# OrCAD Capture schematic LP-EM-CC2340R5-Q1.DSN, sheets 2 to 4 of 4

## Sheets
2 2_Peripherals: size A3
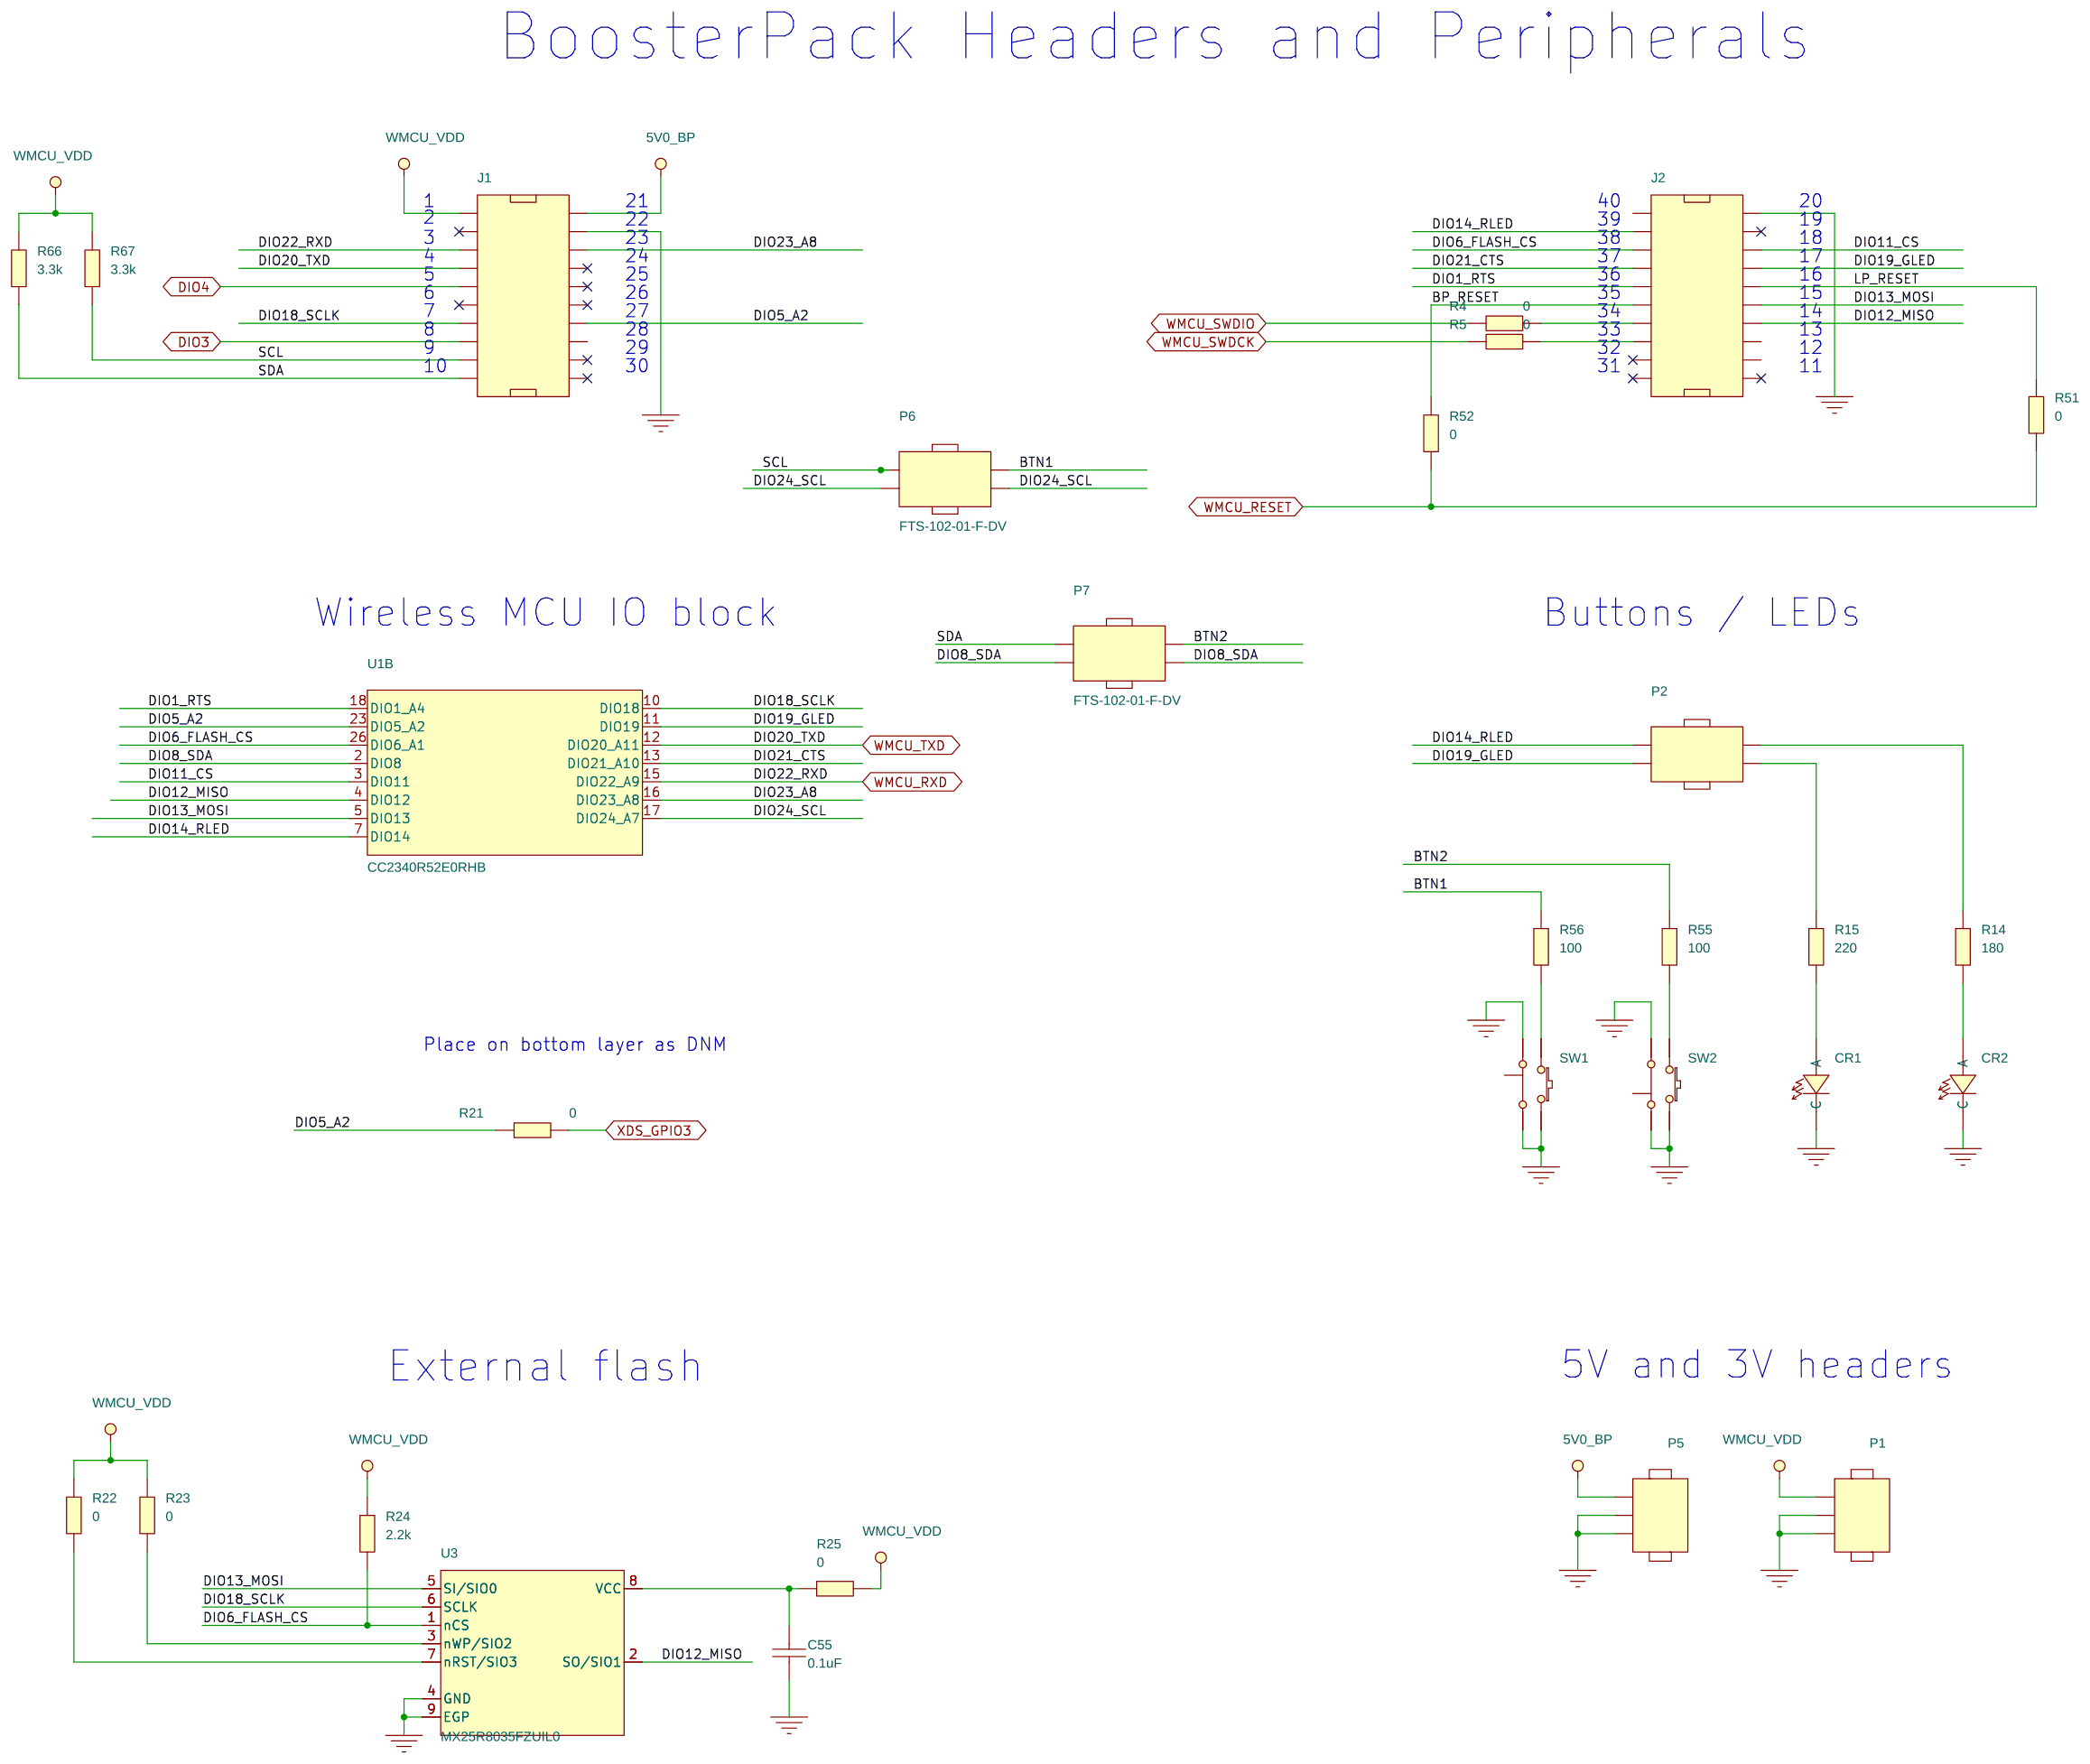
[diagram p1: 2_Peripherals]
3 3_Debugger Interface: size A3
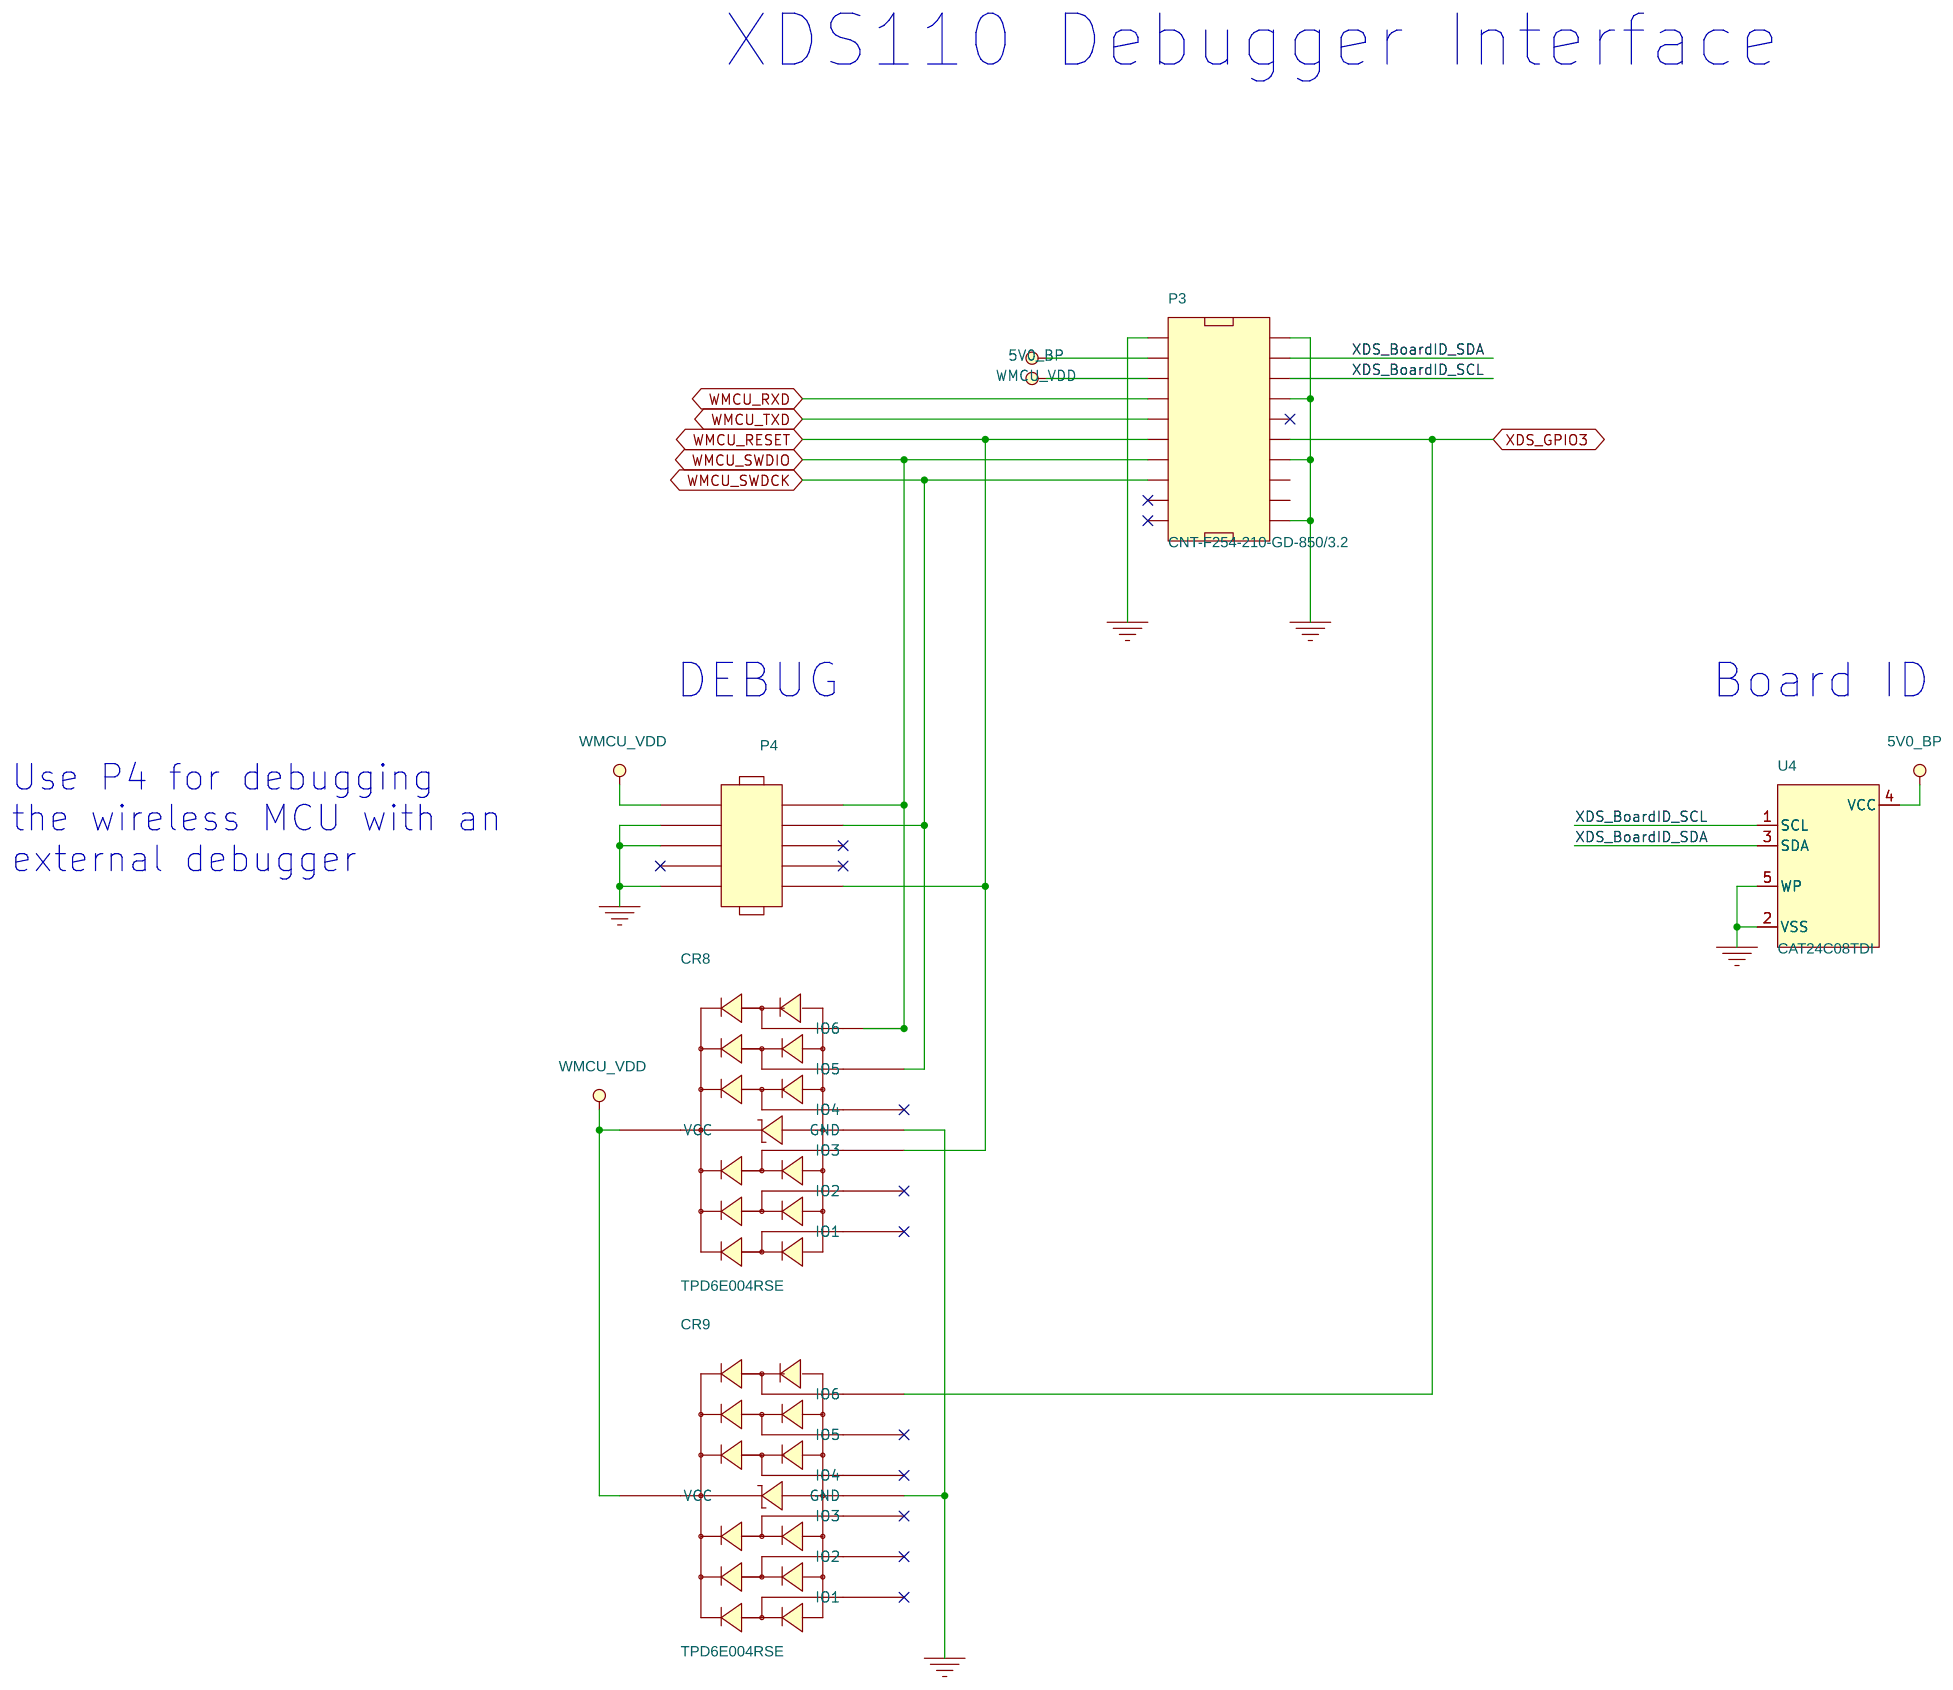
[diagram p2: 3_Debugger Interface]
4 4_Mech: size A3
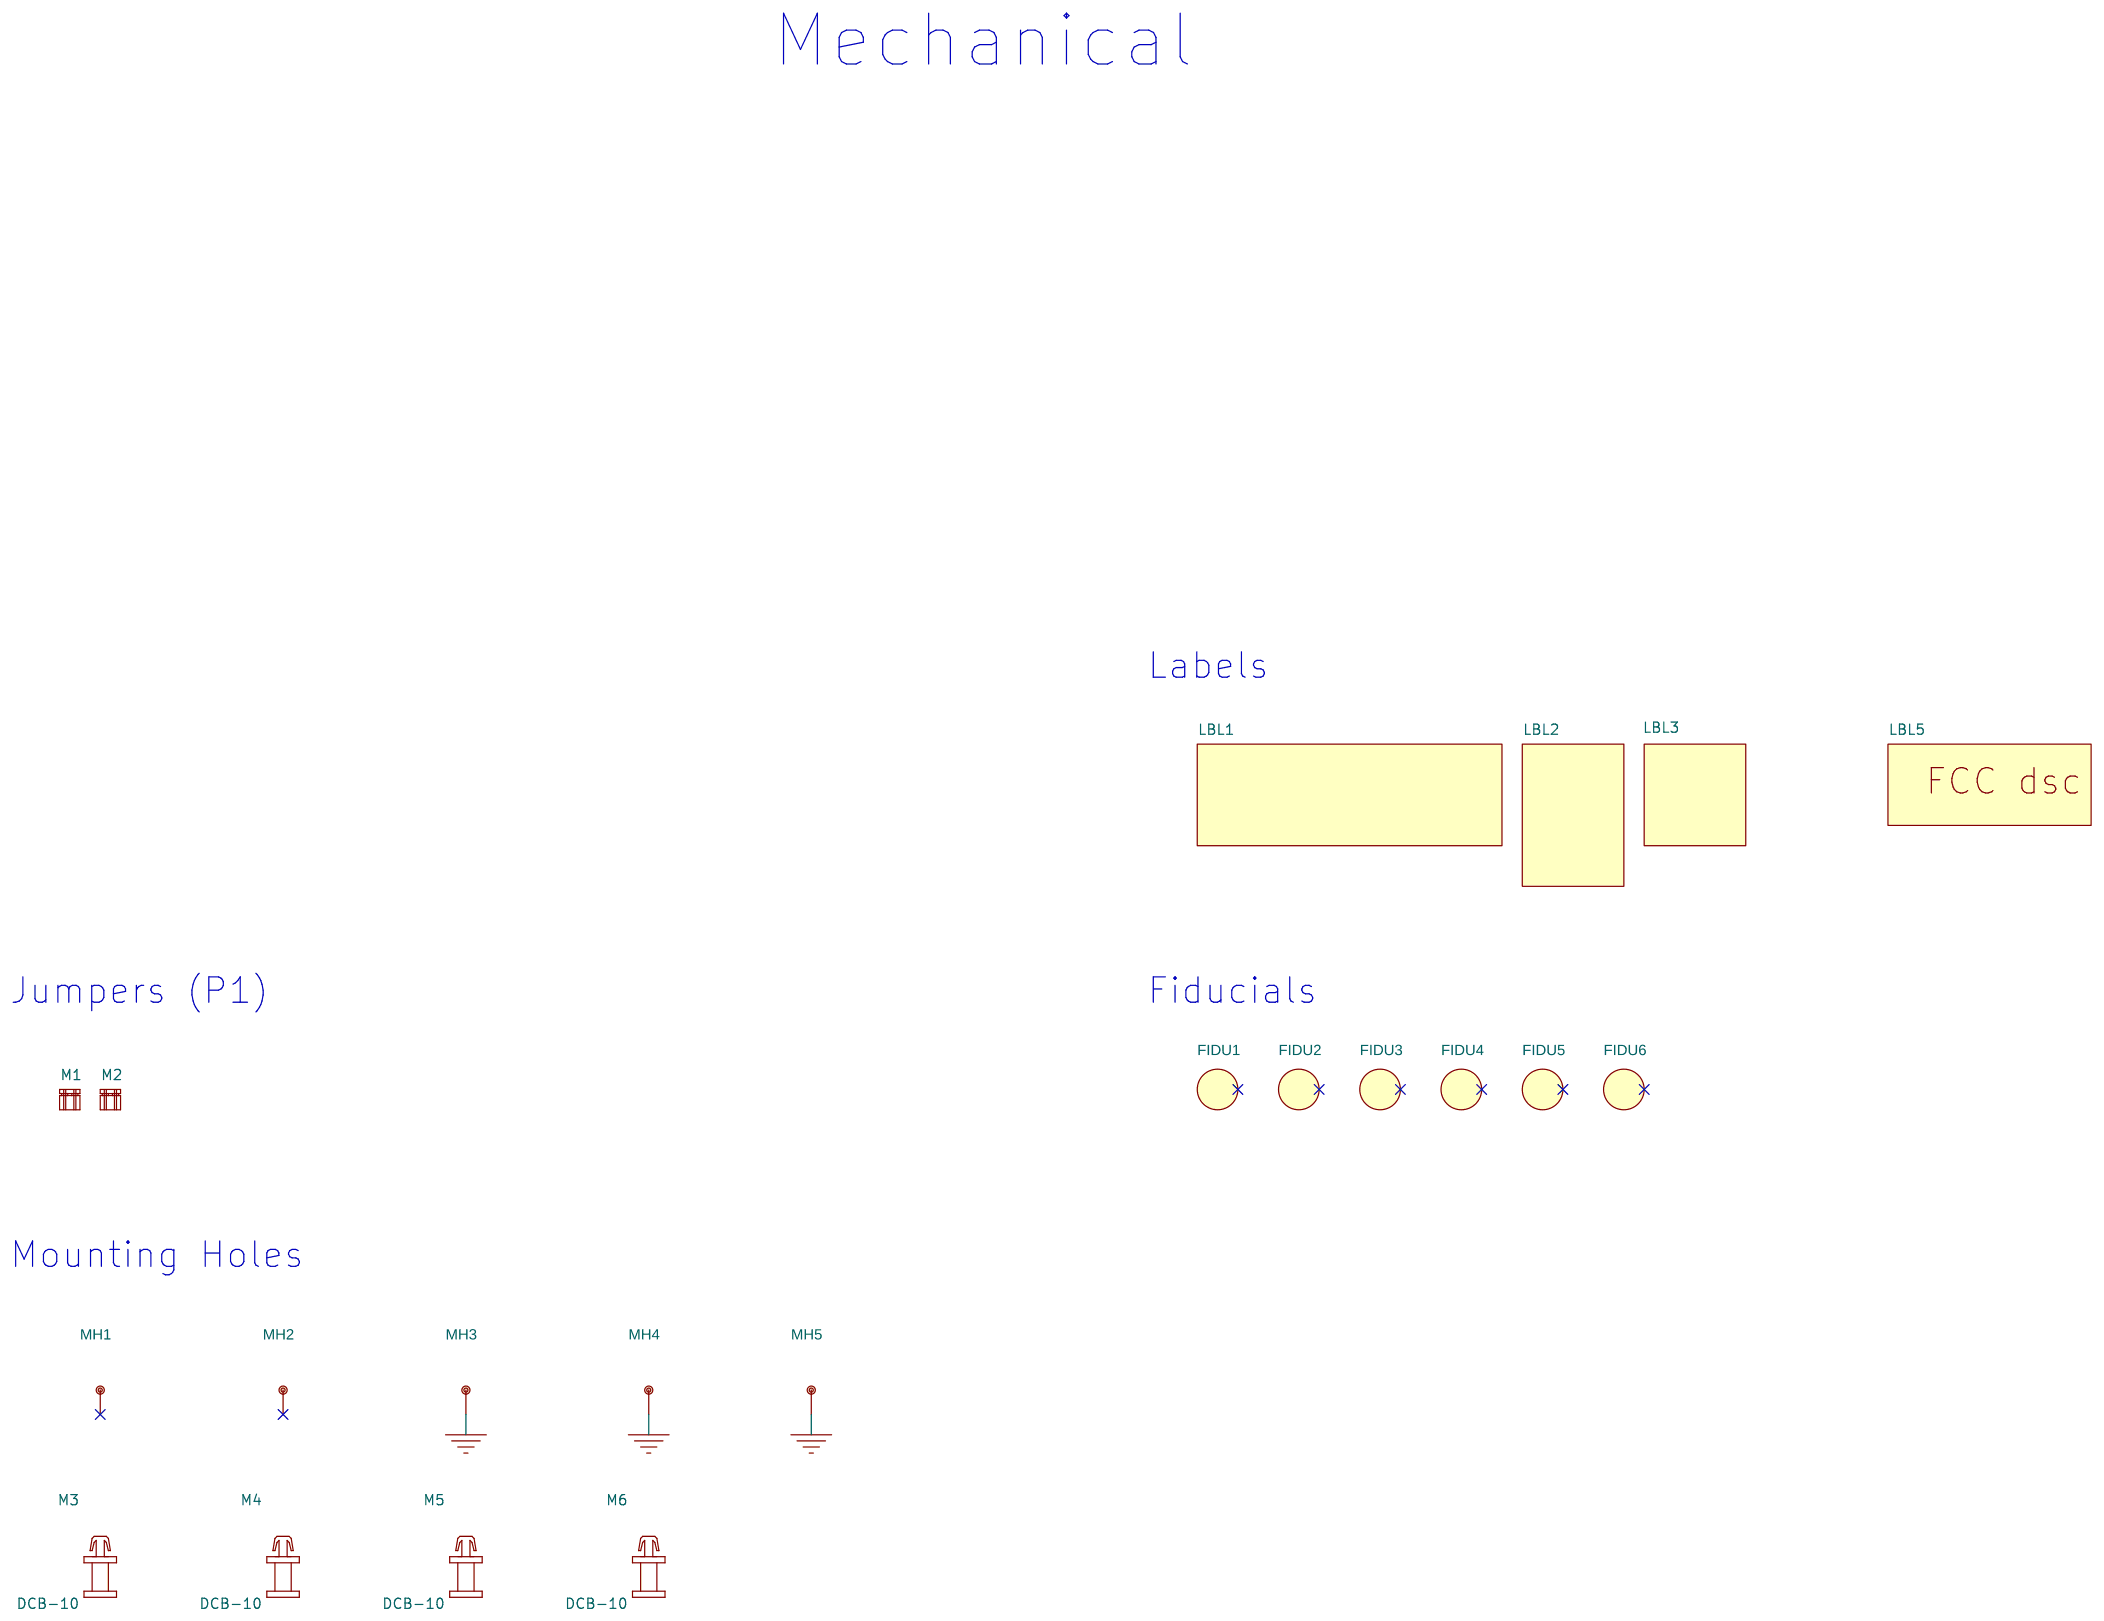
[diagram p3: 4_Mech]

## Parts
sheet 2_Peripherals
C55  0.1uF  [CAPC0603X35B2N]
CR1  LPL296-J2L2-25  [LEDC1707X65N]
CR2  LS L296-P2Q2-1  [LEDC1708X67N]
J1  SSQ-110-23-L-D  [SAMTEC_SSQ11023LD_A2B]
J2  SSQ-110-23-L-D  [SAMTEC_SSQ11023LD_A2B]
P1  BB02-HC031-KB1-603000  [GRADCONN_BB02HC031KB1603000_A2B]
P2  BB02-HJ041-KB1-603000  [GRADCONN_BB02HJ041KB1603000_A2B]
P5  BB02-HC031-KB1-603000  [GRADCONN_BB02HC031KB1603000_A2B]
P6  FTS-102-01-F-DV  [SAMTEC_FTS10201FDV_A2N]
P7  FTS-102-01-F-DV  [SAMTEC_FTS10201FDV_A2N]
R4  0  [RESC1608X55A2N]
R5  0  [RESC1608X55A2N]
R14  180  [RESC1005X40B2N]
R15  220  [RESC1005X40B2N]
R21  0  [RESC1608X55A2N]
R22  0  [RESC1608X55A2N]
R23  0  [RESC1608X55A2N]
R24  2.2k  [RESC1005X40B2N]
R25  0  [RESC1608X55A2N]
R51  0  [RESC1608X55A2N]
R52  0  [RESC1608X55A2N]
R55  100  [RESC1005X40B2N]
R56  100  [RESC1005X40B2N]
R66  3.3k  [RESC1005X40B2N]
R67  3.3k  [RESC1005X40B2N]
SW1  1188E-1K2  [SW_1188E1K2V_A2N]
SW2  1188E-1K2  [SW_1188E1K2V_A2N]
U1  CC2340R52E0RHB  [QFNFC50P500X500X100-33B2N]  (sections A,B)
U3  MX25R8035FZUIL0  [SON50P300X200X60-9B2N]
sheet 3_Debugger Interface
CR8  TPD6E004RSE  [QFNFC50P150X150X60-8A2N]
CR9  TPD6E004RSE  [QFNFC50P150X150X60-8A2N]
P3  CNT-F254-210-GD-850/3.2  [CNT_CNTF254210GD85032_A2B]
P4  FTSH-105-01-F-DV-K  [SAMTEC_FTSH-105-01-F-DV-K-10L]
U4  CAT24C08TDI  [SOT95P280X100-5A2N]
sheet 4_Mech
FIDU1  FIDU_1.27mm  [FID127X142]
FIDU2  FIDU_1.27mm  [FID127X142]
FIDU3  FIDU_1.27mm  [FID127X142]
FIDU4  FIDU_1.27mm  [FID127X142]
FIDU5  FIDU_1.27mm  [FID127X142]
FIDU6  FIDU_1.27mm  [FID127X142]
LBL1  TI_LOGO  [TI_LOGO_1]
LBL2  TRASH_7mm  [TRASH_7MM]
LBL3  ESD_LABEL_5x5mm  [ESD_LABEL_5x5]
LBL5  LABEL_FOR_EVALUATION_ONLY  [LABEL_FOR_EVALUATION_ONLY]
M1  SNT-100-BK-G  [SAMTEC_SNT100BKG]
M2  SNT-100-BK-G  [SAMTEC_SNT100BKG]
M3  DCB-10  [MECH_DCB10_A2B]
M4  DCB-10  [MECH_DCB10_A2B]
M5  DCB-10  [MECH_DCB10_A2B]
M6  DCB-10  [MECH_DCB10_A2B]
MH1  HOLE_3.2mm_PTH  [MTG320_380]
MH2  HOLE_3.2mm_PTH  [MTG320_380]
MH3  HOLE_3.2mm_PTH  [MTG320_380]
MH4  HOLE_3.2mm_PTH  [MTG320_380]
MH5  HOLE_1.1mm_PTH  [MTG110_170]

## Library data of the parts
C55 = CAPACITOR: CAPACITOR, CERAMIC X7S, 0.1uF, 10V, -10%/+10%, -55DEGC/+125DEGC, 0201, SMD; ALT_SYMBOLS: CAPC0603X35B2L,CAPC0603X35B2M; Additional Datasheet URL: https://search.murata.co.jp/Ceramy/image/img/A01X/G101/ENG/GRM033C71A104KE14-01A.pdf; AutoDoc File: https://notefied-dynamic-precision.com/DB/Apps/Desktop/Item/Object.aspx?id=115293; BU Name: TEXAS INSTRUMENTS NORWAY; Budgetary Price: 0.01328 USD; Client Status: UNDER_REVIEW; Datasheet URL: https://www.murata.com/-/media/webrenewal/support/library/catalog/products/capacitor/ceramiccapacitor/c02e.ashx?la=en-gb; Datasheet URL 1: http://psearch.en.murata.com/capacitor/product/GRM155R71E104KE14%23.pdf; Datasheet URL 2: http://search.murata.co.jp/Ceramy/image/img/w_hinm/L0005E.pdf; Definied Quality: INDUSTRIAL; Dielectric Type: X7S; Esd Level: N/A; Lead Time: 23; LifeCycle Status: ACTIVE; MPN: CAPACITOR_0402_100nF_X7R_M_+/-10%_10V; MPN Status: ACTIVE; MSL: N/A; MTBF: N/A; MTBF Standard: N/A; Manufacturer: MANUFACTURER SELECTION; Mass: 0.00033g; Max Oper Temp: +125DEGC; Max Tol: +10%; Maximum Operating Temperature: +125DEGC; Maximum Tolerance: +10%; Min Oper Temp: -55DEGC; Min Tol: -10%; Minimum Operating Temperature: -55DEGC; Minimum Tolerance: -10%; Mounting Type: SMD; NOTE Status: PREFERRED; NOTEfied URL: https://notefied-dynamic-precision.com/NOTEfiedWebInterface/part/show?partNumber=02-10308; Old Footprint: CAPC1005X60N; PCB Package: 0201; Packing Size: 15000; Packing Type: Tape & Reel; Part Number: 02-10308; Part Type: Capacitor|CERAMIC|0201|STANDARD; REACH/SVHC Compliance: Compliant; REACH/SVHC Details: SVHC List Version Jan 19, 2021; REACH/SVHC Source: REACH Declaration; REACH/SVHC Status: Unaffected; REACH/SVHC_COMPLIANCE: COMPLIANT; REACH/SVHC_DETAILS: SVHC LIST VERSION Jun 20, 2016; REACH/SVHC_SOURCE: REACH DECLARATION; REACH/SVHC_STATUS: UNAFFECTED; ROHS: Compliant; Rated Voltage: 10V; Revision: R001; RoHS Status: ROHS_COMPLIANT; Rtd Voltage: 25V; Status: Released; Texas Part Status: Under Review; Type: Capacitor; Vendor: MURATA; Vendor Part Number: GRM033C71A104KE14D; Vendor Part Status: Active; WEIGHT: 0.0016g
CR1 = LED: OPTO, LED, InGaAlP, GREEN, 560nm, 2V, 0.02A, 0603, SMD; ALT_SYMBOLS: LEDC1707X65L,LEDC1707X65M; Additional Datasheet URL: https://www.osram.com/ecat/SMARTLED%C2%AE%200603%20LP%20L296/com/en/class_pim_web_catalog_103489/prd_pim_device_2190983/; AutoDoc File: http://notefied-dynamic-precision.com/DB/Apps/Desktop/Item/Object.aspx?id=81622; Budget Currency: USD; Budget Price: 0.1263; CLASS: IC; Country of Origin: Missing Info; Datasheet URL: https://dammedia.osram.info/media/resource/hires/osram-dam-5662674/LP%20L296_EN.pdf; Datasheet URL 1: N/A; Datasheet URL 2: http://catalog.osram-os.com/jsp/download.jsp?rootPath=/media/&name=LP_L296.pdf&docPath=Graphics/00077128_0.pdf&url=/media//_en/Graphics/00077128_0.pdf; Definied Quality: INDUSTRIAL; Esd Level: HBM 2kV; FPLIST: LEDC1707X65N,LEDC1707X65L,LEDC1707X65M; MPN: LP L296-J2L2-25; MPN Status: NRND; MSL: 2; MTBF: N/A; MTBF Standard: N/A; Manufacturer: OSRAM; Mass: 0.0016g; Max Oper Temp: +100DEGC; Maximum Operating Temperature: +100DEGC; Min Oper Temp: -40DEGC; Minimum Operating Temperature: -40DEGC; Mounting Type: SMD; NOTE Status: NOT_PREFERRED; NOTEfied URL: https://notefied-dynamic-precision.com/NOTEfiedWebInterface/part/show?partNumber=15-01023; PCB Package: 0603; Packing Size: 5000; Packing Type: Tape & Reel; Part Number: 15-01023; Part Type: Opto|LED|0603; REACH/SVHC Compliance: Compliant; REACH/SVHC Details: SVHC List Version Jan 12, 2017; REACH/SVHC Source: REACH Declaration; REACH/SVHC Status: Unaffected; ROHS: Compliant; Rated Current: 0.02A; Rated Voltage: 2V; Revision: R029; RoHS Status: ROHS_COMPLIANT; Rtd Current: 0.02A; Rtd Power: 0.08W; Rtd Voltage: 2V; Status: Released; Type: Opto; Vendor: OSRAM; Vendor Part Number: LP L296-J2L2-25; Vendor Part Status: Active; WEIGHT: 0.002g
CR2 = LED: OPTO, LED, RED, 630nm, 2V, 0.02A, 0603, SMD; ALT_SYMBOLS: LEDC1708X67L,LEDC1708X67M; Additional Datasheet URL: https://www.osram.com/ecat/SMARTLED%C2%AE%200603%20LS%20L296/com/en/class_pim_web_catalog_103489/prd_pim_device_2190979/; AutoDoc File: http://notefied-dynamic-precision.com/DB/Apps/Desktop/Item/Object.aspx?id=88355; Budget Currency: USD; Budget Price: 0.089; CLASS: IC; Country of Origin: Missing Info; Datasheet URL: https://dammedia.osram.info/media/resource/hires/osram-dam-5361494/LS%20L296_EN.pdf; Datasheet URL 1: http://www.osram-os.com/osram_os/en/products/product-catalog/led-light-emitting-diodes/smartled-0603/ls-l296/index.jsp?search_result=%2fosram_os%2fen%2fsearch%2fadvanced_search.jsp%3faction%3ddosearch%26inp_searchterm_1%3dLS%2bL296-P2Q2-1%26website_name%3; Datasheet URL 2: http://www.osram-os.com/Graphics/XPic5/00077119_0.pdf/LS%20L296%20-%20SMARTLED%200603.pdf; Definied Quality: INDUSTRIAL; Esd Level: HBM 2kV; FPLIST: LEDC1708X67N,LEDC1708X67L,LEDC1708X67M; MPN Status: NRND; MSL: 2; MTBF: N/A; MTBF Standard: N/A; Manufacturer: OSRAM; Mass: 0.0016g; Max Oper Temp: +100DEGC; Maximum Operating Temperature: +100DEGC; Min Oper Temp: -40DEGC; Minimum Operating Temperature: -40DEGC; Mounting Type: SMD; NOTE Status: PREFERRED; NOTEfied URL: https://notefied-dynamic-precision.com/NOTEfiedWebInterface/part/show?partNumber=15-01169; PCB Package: 0603; PPCB Recomendation: Inactive for new design [Alert:0001]; Packing Size: 5000; Packing Type: Tape & Reel; Part Number: 15-01169; Part Type: Opto|LED|0603; REACH/SVHC Compliance: Compliant; REACH/SVHC Details: SVHC List Version Jan 12, 2017; REACH/SVHC Source: REACH Declaration; REACH/SVHC Status: Unaffected; ROHS: Compliant; Rated Current: 0.02A; Rated Voltage: 2V; Revision: R029; RoHS Status: ROHS_COMPLIANT; Rtd Current: 0.06A; Rtd Voltage: 1.8V TO 2.3V; Status: Released; Type: Opto; Vendor: OSRAM; Vendor Part Status: Active; WEIGHT: 0.002g
J1 J2 = CONN_HEADER_2X10_J_S_V1: CONNECTOR, HEADER, FEMALE, STRAIGHT, 2 ROWS, 20 PINS, 2.54mm, PTH; ALT_SYMBOLS: SAMTEC_SSQ11023LD_A2C,SAMTEC_SSQ11023LD_A2A; Additional Datasheet URL: https://suddendocs.samtec.com/prints/ssq-1xx-xx-xxx-x-xx-xxx-xx-x-mkt.pdf; AutoDoc File: http://notefied-dynamic-precision.com/DB/Apps/Desktop/Item/Object.aspx?id=104387; Budget Currency: USD; Budget Price: 2.14; Budgetary Price: 3.17 USD; Country of Origin: China,Costa Rica,Malaysia,Singapore,United States; Datasheet URL: https://suddendocs.samtec.com/catalog_english/ssq_th.pdf; Datasheet URL 1: http://suddendocs.samtec.com/prints/ssq-1xx-xx-xxx-x-xx-xxx-xx-x-mkt.pdf; Datasheet URL 2: http://suddendocs.samtec.com/catalog_english/ssq_th.pdf; Definied Quality: INDUSTRIAL; Esd Level: N/A; FPLIST: SAMTEC_SSQ11023LD_A2B,SAMTEC_SSQ11023LD_A2C,SAMTEC_SSQ11023LD_A2A; LifeCycle Status: ACTIVE; MPN Status: ACTIVE; MSL: N/A; Manufacturer: SAMTEC; Mass: 2.45594g; Max Oper Temp: +125DEGC; Maximum Operating Temperature: +125DEGC; Min Oper Temp: -55DEGC; Minimum Operating Temperature: -55DEGC; Mounting Type: PTH; NOTE Status: PREFERRED; NOTEfied URL: https://notefied-dynamic-precision.com/NOTEfiedWebInterface/part/show?partNumber=06-04997; No Of Pos: 20; No Of Rows: 2; Number of Positions: 20; Number of Rows: 2; Packing Size: 21; Packing Type: Bulk; Part Number: 06-04997; Part Type: Connector|HEADER|STANDARD; Pitch: 2.54mm; REACH/SVHC Compliance: Compliant; REACH/SVHC Details: SVHC List Version Jan 12, 2017; REACH/SVHC Source: REACH Declaration; REACH/SVHC Status: Unaffected; ROHS: Compliant; Rated Current: 6.3A; Revision: R020; RoHS Status: ROHS_COMPLIANT; Rtd Current: 6.3A; Status: Released; Texas Part Status: Under Review; Type: Connector; Vendor: SAMTEC; Vendor Part Status: Active; WEIGHT: 2.45594g
P1 P5 = CONN_HEADER_3_P_S: CONNECTOR, HEADER, MALE, STRAIGHT, 1 ROW, 3 PINS, PITCH 2.54mm, PTH; ALT_SYMBOLS: GRADCONN_BB02HC031KB1603000_A2C,GRADCONN_BB02HC031KB1603000_A2A; Additional Datasheet URL: https://www.gradconn.com/Files/Drawings/BB02-HC.pdf; AutoDoc File: http://notefied-dynamic-precision.com/DB/Apps/Desktop/Item/Object.aspx?id=104636; Country of Origin: Missing Info; Datasheet URL: https://www.gradconn.com/Files/Specs/BTB-2.54mm-Header-specification.pdf; Datasheet URL 1: http://www.gradconn.com/Files/Drawings/BB02-HC.pdf; Datasheet URL 2: http://www.gradconn.com/Files/Specs/BTB-2.54mm-Header-specification.pdf; FPLIST: GRADCONN_BB02HC031KB1603000_A2B,GRADCONN_BB02HC031KB1603000_A2C,GRADCONN_BB02HC031KB1603000_A2A; MPN Status: ACTIVE; Manufacturer: GRADCONN; Mass: N/A; Max Oper Temp: +105DEGC; Maximum Operating Temperature: +105DEGC; Min Oper Temp: -40DEGC; Minimum Operating Temperature: -40DEGC; Mounting Type: PTH; NOTE Status: PREFERRED; NOTEfied URL: https://notefied-dynamic-precision.com/NOTEfiedWebInterface/part/show?partNumber=06-05038; No Of Pos: 3; No Of Rows: 1; Number of Positions: 3; Number of Rows: 1; Packing Size: N/A; Packing Type: Missing Info; Part Number: 06-05038; Part Type: Connector|HEADER|STANDARD; Pitch: 2.54mm; REACH/SVHC Compliance: Compliant; REACH/SVHC Details: SVHC List Version Jun 20, 2016; REACH/SVHC Source: RoHS & REACH Declaration; REACH/SVHC Status: Unaffected; ROHS: Compliant; Rated Current: 3A; Rated Voltage: 250V; Revision: R021; RoHS Status: ROHS_COMPLIANT; Rtd Current: 3A; Rtd Voltage: 250V; Status: Released; Texas Part Status: Under Review; Type: Connector; Vendor: GRADCONN; Vendor Part Status: Active
P2 = CONN_HEADER_2X2_P: CONNECTOR, HEADER, MALE, STRAIGHT, 2 ROWS, 4 PINS, PITCH 2.54mm, PTH; ALT_SYMBOLS: GRADCONN_BB02HJ041KB1603000_A2C,GRADCONN_BB02HJ041KB1603000_A2A; Additional Datasheet URL: https://www.gradconn.com/Files/Drawings/BB02-HJ.pdf; AutoDoc File: http://notefied-dynamic-precision.com/DB/Apps/Desktop/Item/Object.aspx?id=104391; Country of Origin: Missing Info; Datasheet URL: https://www.gradconn.com/Files/Specs/BTB-2.54mm-Header-specification.pdf; Datasheet URL 1: http://www.gradconn.com/Files/Drawings/BB02-HJ.pdf; Datasheet URL 2: http://www.gradconn.com/Files/Specs/BTB-2.54mm-Header-specification.pdf; FPLIST: GRADCONN_BB02HJ041KB1603000_A2B,GRADCONN_BB02HJ041KB1603000_A2C,GRADCONN_BB02HJ041KB1603000_A2A; MPN Status: ACTIVE; Manufacturer: GRADCONN; Mass: N/A; Max Oper Temp: +105DEGC; Maximum Operating Temperature: +105DEGC; Min Oper Temp: -40DEGC; Minimum Operating Temperature: -40DEGC; Mounting Type: PTH; NOTE Status: PREFERRED; NOTEfied URL: https://notefied-dynamic-precision.com/NOTEfiedWebInterface/part/show?partNumber=06-04999; No Of Pos: 4; No Of Rows: 2; Number of Positions: 4; Number of Rows: 2; Packing Size: N/A; Packing Type: Missing Info; Part Number: 06-04999; Part Type: Connector|HEADER|STANDARD; Pitch: 2.54mm; REACH/SVHC Compliance: Compliant; REACH/SVHC Details: SVHC List Version Jun 20, 2016; REACH/SVHC Source: RoHS & REACH Declaration; REACH/SVHC Status: Unaffected; ROHS: Compliant; Rated Current: 3A; Revision: R021; RoHS Status: ROHS_COMPLIANT; Rtd Current: 3A; Status: Released; Texas Part Status: Under Review; Type: Connector; Vendor: GRADCONN; Vendor Part Status: Active
P6 P7 = CONN_HEADER_2X2_P_V2: CONNECTOR, HEADER, MALE, STRAIGHT, 2 ROW(S), 4 PINS, PITCH 1.27mm, SMD; ALT_SYMBOLS: SAMTEC_FTS10201FDV_A2L,SAMTEC_FTS10201FDV_A2M; Additional Datasheet URL: https://suddendocs.samtec.com/prints/fts-1xx-xx-xx-xx-xx-mkt.pdf; Budgetary Price: 0.90142 USD; Country of Origin: China,Costa Rica,Malaysia,Singapore,Taiwan,United States,Vietnam; Datasheet URL: https://suddendocs.samtec.com/catalog_english/fts.pdf; Lead Time: 9; Mass: 0.04709g; Maximum Operating Temperature: +125DEGC; Minimum Operating Temperature: -55DEGC; Mounting Type: SMD; NOTEfied URL: https://notefied-dynamic-precision.com/NOTEfiedWebInterface/part/show?partNumber=06-08198; Number of Positions: 4; Number of Rows: 2; Packing Size: 725; Packing Type: Tape & Reel; Part Number: 06-08198; Part Type: Connector|HEADER|STANDARD; Pitch: 1.27mm; REACH/SVHC Details: SVHC List Version; ROHS: Compliant; Rated Current: 3.4A; Revision: R011; Status: Released; Type: Connector; Vendor: SAMTEC; Vendor Part Number: FTS-102-01-F-DV-TR; Vendor Part Status: Active
R4 R5 R22 R23 R25 R51 R52 = RESISTOR: RESISTOR, THICK FILM, 0, 0R/+0.02R, 0.1W, 2A, -55DEGC/+155DEGC, 0603, SMD; ALT_SYMBOLS: RESC1608X55A2L,RESC1608X55A2M; Additional Datasheet URL: N/A; AutoDoc File: https://notefied-dynamic-precision.com/DB/Apps/Desktop/Item/Object.aspx?id=94847; BU Name: DYNAMIC PRECISION GDANSK; Budget Currency: USD; Budget Price: 0.0016; Budgetary Price: 0.005 EUR; Client Status: UNDER_REVIEW; Country of Origin: Israel; Datasheet URL: http://www.vishay.com/docs/20035/dcrcwe3.pdf; Datasheet URL 1: http://www.vishay.com/docs/20035/dcrcwe3.pdf; Datasheet URL 2: N/A; Esd Level: N/A; Lead Time: 29; LifeCycle Status: ACTIVE; MPN: DNM; MPN Status: ACTIVE; MSL: N/A; MTBF: N/A; MTBF Standard: N/A; Manufacturer: DO NOT MOUNT; Mass: 0.002g; Max Oper Temp: +155DEGC; Max TC: N/A; Max Tol: +0.02R; Maximum Operating Temperature: +155DEGC; Maximum Temperature Coefficient: N/A; Maximum Tolerance: +0.02R; Min Oper Temp: -55DEGC; Min TC: N/A; Min Tol: 0R; Minimum Operating Temperature: -55DEGC; Minimum Temperature Coeficient: N/A; Minimum Tolerance: 0R; Mounting Type: SMD; NOTE Status: PREFERRED; NOTEfied URL: https://notefied-dynamic-precision.com/NOTEfiedWebInterface/part/show?partNumber=01-20043; Old Footprint: RESC1608X55N,0603; PCB Package: 0603; Packing Size: 20000; Packing Type: Tape & Reel; Part Number: 01-20043; Part Type: Resistor|0603|JUMPER; REACH/SVHC Compliance: Compliant; REACH/SVHC Details: SVHC List Version Jun 15, 2015; REACH/SVHC Source: Material Declaration; REACH/SVHC Status: Unaffected; REACH/SVHC_COMPLIANCE: COMPLIANT; REACH/SVHC_DETAILS: SVHC LIST VERSION Jun 15, 2015; REACH/SVHC_SOURCE: MATERIAL DECLARATION; REACH/SVHC_STATUS: UNAFFECTED; ROHS: Exempt; Rated Current: 2A; Rated Power: 0.1W; Rated Voltage: N/A; Resistor Type: THICK FILM; Revision: R010; RoHS Status: ROHS_COMPLIANT_WITH_EXEMPTION; Rtd Current: N/A; Rtd Power: 0.1W; Rtd Voltage: 75V; Status: Released; Type: Resistor; Vendor: VISHAY; Vendor Part Number: CRCW06030000Z0EC; Vendor Part Status: Active; WEIGHT: 0.002g
R14 = RESISTOR: RESISTOR, THICK FILM, 180, -5%/+5%, 0.063W, 50V, -55DEGC/+155DEGC, 0402, SMD; Additional Datasheet URL: N/A; AutoDoc File: https://notefied-dynamic-precision.com/DB/Apps/Desktop/Item/Object.aspx?id=113318; BU Name: TEXAS INSTRUMENTS NORWAY; Budget Currency: EUR; Budget Price: 0.014; Budgetary Price: 0.014 EUR; Client Status: UNDER_REVIEW; Country of Origin: Missing Info; Datasheet URL: https://www.vishay.com/docs/20035/dcrcwe3.pdf; Datasheet URL 1: http://www.vishay.com/docs/20035/dcrcwe3.pdf; Datasheet URL 2: N/A; Definied Quality: INDUSTRIAL; Esd Level: N/A; Exclusive for Customers: TEXAS INSTRUMENTS NORWAY; Lead Time: 18; LifeCycle Status: ACTIVE; MPN: RESISTOR_0402_180_+/-5%_50V_0.063W_M_+/-200ppm; MPN Status: ACTIVE; MSL: N/A; MTBF: N/A; MTBF Standard: N/A; Manufacturer: MANUFACTURER SELECTION; Mass: 0.00065g; Max Oper Temp: +155DEGC; Max TC: +200PPM/DEGC; Max Tol: +5%; Maximum Operating Temperature: +155DEGC; Maximum Temperature Coefficient: +200PPM/DEGC; Maximum Tolerance: +5%; Min Oper Temp: -55DEGC; Min TC: -200PPM/DEGC; Min Tol: -5%; Minimum Operating Temperature: -55DEGC; Minimum Temperature Coeficient: -200PPM/DEGC; Minimum Tolerance: -5%; Mounting Type: SMD; NOTE Status: PREFERRED; NOTEfied URL: https://notefied-dynamic-precision.com/NOTEfiedWebInterface/part/show?partNumber=01-22345; Notes: Standard item: Duplicate Reason: custom footprint for TEXAS INSTRUMENTS NORWAY.; Old Footprint: RESC1005X40N; PCB Package: 0402; Packing Size: 10000; Packing Type: Tape & Reel; Part Number: 01-22345; Part Type: Resistor|0402|STANDARD; REACH/SVHC Compliance: Compliant; REACH/SVHC Details: SVHC List Version Jun 20, 2016; REACH/SVHC Source: Material Declaration; REACH/SVHC Status: Unaffected; REACH/SVHC_COMPLIANCE: COMPLIANT; REACH/SVHC_DETAILS: SVHC LIST VERSION Jun 20, 2016; REACH/SVHC_SOURCE: MATERIAL DECLARATION; REACH/SVHC_STATUS: UNAFFECTED; ROHS: Exempt; Rated Current: N/A; Rated Power: 0.063W; Rated Voltage: 50V; Resistor Type: THICK FILM; Revision: R021; RoHS Status: ROHS_COMPLIANT_WITH_EXEMPTION; Rtd Current: N/A; Rtd Power: 0.063W; Rtd Voltage: 50V; Status: Released; Texas Part Status: Under Review; Type: Resistor; Vendor: VISHAY; Vendor Part Number: CRCW0402180RJNED; Vendor Part Status: Active; WEIGHT: 0.00065g
R15 = RESISTOR: RESISTOR, THICK FILM, 220, -5%/+5%, 0.063W, 50V, -55DEGC/+155DEGC, 0402, SMD; Additional Datasheet URL: N/A; AutoDoc File: https://notefied-dynamic-precision.com/DB/Apps/Desktop/Item/Object.aspx?id=113319; BU Name: TEXAS INSTRUMENTS NORWAY; Budget Currency: EUR; Budget Price: 0.014; Budgetary Price: 0.014 EUR; Client Status: UNDER_REVIEW; Country of Origin: Israel; Datasheet URL: https://www.vishay.com/docs/20035/dcrcwe3.pdf; Datasheet URL 1: http://www.vishay.com/docs/20035/dcrcwe3.pdf; Datasheet URL 2: N/A; Definied Quality: INDUSTRIAL; Esd Level: N/A; Exclusive for Customers: TEXAS INSTRUMENTS NORWAY; Lead Time: 18; LifeCycle Status: ACTIVE; MPN: RESISTOR_0402_220_+/-5%_50V_0.063W_M_+/-200ppm; MPN Status: ACTIVE; MSL: N/A; MTBF: N/A; MTBF Standard: N/A; Manufacturer: MANUFACTURER SELECTION; Mass: 0.00065g; Max Oper Temp: +155DEGC; Max TC: +200PPM/DEGC; Max Tol: +5%; Maximum Operating Temperature: +155DEGC; Maximum Temperature Coefficient: +200PPM/DEGC; Maximum Tolerance: +5%; Min Oper Temp: -55DEGC; Min TC: -200PPM/DEGC; Min Tol: -5%; Minimum Operating Temperature: -55DEGC; Minimum Temperature Coeficient: -200PPM/DEGC; Minimum Tolerance: -5%; Mounting Type: SMD; NOTE Status: PREFERRED; NOTEfied URL: https://notefied-dynamic-precision.com/NOTEfiedWebInterface/part/show?partNumber=01-22346; Notes: Standard item: Duplicate Reason: custom footprint for TEXAS INSTRUMENTS NORWAY.; Old Footprint: RESC1005X40N; PCB Package: 0402; Packing Size: 10000; Packing Type: Tape & Reel; Part Number: 01-22346; Part Type: Resistor|0402|STANDARD; REACH/SVHC Compliance: Compliant; REACH/SVHC Details: SVHC List Version Jun 20, 2016; REACH/SVHC Source: Material Declaration; REACH/SVHC Status: Unaffected; REACH/SVHC_COMPLIANCE: COMPLIANT; REACH/SVHC_DETAILS: SVHC LIST VERSION Jun 20, 2016; REACH/SVHC_SOURCE: MATERIAL DECLARATION; REACH/SVHC_STATUS: UNAFFECTED; ROHS: Exempt; Rated Current: N/A; Rated Power: 0.063W; Rated Voltage: 50V; Resistor Type: THICK FILM; Revision: R021; RoHS Status: ROHS_COMPLIANT_WITH_EXEMPTION; Rtd Current: N/A; Rtd Power: 0.063W; Rtd Voltage: 50V; Status: Released; Texas Part Status: Under Review; Type: Resistor; Vendor: VISHAY; Vendor Part Number: CRCW0402220RJNED; Vendor Part Status: Active; WEIGHT: 0.00065g
R21 = RESISTOR: RESISTOR, THICK FILM, 0, 0R/+0.02R, 0.1W, 75V, -55DEGC/+155DEGC, 0603, SMD; ALT_SYMBOLS: RESC1608X55A2L,RESC1608X55A2M; Additional Datasheet URL: N/A; AutoDoc File: https://notefied-dynamic-precision.com/DB/Apps/Desktop/Item/Object.aspx?id=94847; BU Name: DYNAMIC PRECISION GDANSK; Budget Currency: USD; Budget Price: 0.0016; Budgetary Price: 0.0016 USD; Client Status: UNDER_REVIEW; Country of Origin: Israel; Datasheet URL: http://www.vishay.com/docs/20035/dcrcwe3.pdf; Datasheet URL 1: http://www.vishay.com/docs/20035/dcrcwe3.pdf; Datasheet URL 2: N/A; Esd Level: N/A; Lead Time: 12; LifeCycle Status: ACTIVE; MPN: DNM; MPN Status: ACTIVE; MSL: N/A; MTBF: N/A; MTBF Standard: N/A; Manufacturer: DO NOT MOUNT; Mass: 0.002g; Max Oper Temp: +155DEGC; Max TC: N/A; Max Tol: +0.02R; Maximum Operating Temperature: +155DEGC; Maximum Temperature Coefficient: N/A; Maximum Tolerance: +0.02R; Min Oper Temp: -55DEGC; Min TC: N/A; Min Tol: 0R; Minimum Operating Temperature: -55DEGC; Minimum Temperature Coeficient: N/A; Minimum Tolerance: 0R; Mounting Type: SMD; NOTE Status: PREFERRED; NOTEfied URL: https://notefied-dynamic-precision.com/NOTEfiedWebInterface/part/show?partNumber=01-20043; Old Footprint: RESC1608X55N,0603; PCB Package: 0603; Packing Size: 20000; Packing Type: Tape & Reel; Part Number: 01-20043; Part Type: Resistor|0603|JUMPER; REACH/SVHC Compliance: Compliant; REACH/SVHC Details: SVHC List Version Jun 15, 2015; REACH/SVHC Source: Material Declaration; REACH/SVHC Status: Unaffected; REACH/SVHC_COMPLIANCE: COMPLIANT; REACH/SVHC_DETAILS: SVHC LIST VERSION Jun 15, 2015; REACH/SVHC_SOURCE: MATERIAL DECLARATION; REACH/SVHC_STATUS: UNAFFECTED; ROHS: Exempt; Rated Current: N/A; Rated Power: 0.1W; Rated Voltage: 75V; Resistor Type: THICK FILM; Revision: R004; RoHS Status: ROHS_COMPLIANT_WITH_EXEMPTION; Rtd Current: N/A; Rtd Power: 0.1W; Rtd Voltage: 75V; Status: Released; Type: Resistor; Vendor: VISHAY; Vendor Part Number: CRCW06030000Z0EC; Vendor Part Status: Active; WEIGHT: 0.002g
R24 = RESISTOR: RESISTOR, THICK FILM, 2.2k, -5%/+5%, 0.063W, 50V, -55DEGC/+155DEGC, 0402, SMD; Additional Datasheet URL: N/A; AutoDoc File: https://notefied-dynamic-precision.com/DB/Apps/Desktop/Item/Object.aspx?id=114560; BU Name: TEXAS INSTRUMENTS NORWAY; Budget Currency: EUR; Budget Price: 0.014; Budgetary Price: 0.014 EUR; Client Status: UNDER_REVIEW; Country of Origin: Israel; Datasheet URL: https://www.vishay.com/docs/20035/dcrcwe3.pdf; Datasheet URL 1: http://www.vishay.com/docs/20035/dcrcwe3.pdf; Datasheet URL 2: N/A; Definied Quality: INDUSTRIAL; Esd Level: N/A; Exclusive for Customers: TEXAS INSTRUMENTS NORWAY; Lead Time: 18; LifeCycle Status: ACTIVE; MPN: RESISTOR_0402_2.2k_+/-5%_50V_0.063W_M_+/-200ppm; MPN Status: ACTIVE; MSL: N/A; MTBF: N/A; MTBF Standard: N/A; Manufacturer: MANUFACTURER SELECTION; Mass: 0.00065g; Max Oper Temp: +155DEGC; Max TC: +200PPM/DEGC; Max Tol: +5%; Maximum Operating Temperature: +155DEGC; Maximum Temperature Coefficient: +200PPM/DEGC; Maximum Tolerance: +5%; Min Oper Temp: -55DEGC; Min TC: -200PPM/DEGC; Min Tol: -5%; Minimum Operating Temperature: -55DEGC; Minimum Temperature Coeficient: -200PPM/DEGC; Minimum Tolerance: -5%; Mounting Type: SMD; NOTE Status: PREFERRED; NOTEfied URL: https://notefied-dynamic-precision.com/NOTEfiedWebInterface/part/show?partNumber=01-22487; Notes: Standard item: Duplicate Reason: custom footprint for TEXAS INSTRUMENTS NORWAY.; Old Footprint: RESC1005X40N; PCB Package: 0402; Packing Size: 10000; Packing Type: Tape & Reel; Part Number: 01-22487; Part Type: Resistor|0402|STANDARD; REACH/SVHC Compliance: Compliant; REACH/SVHC Details: SVHC List Version Jun 20, 2016; REACH/SVHC Source: Material Declaration; REACH/SVHC Status: Unaffected; REACH/SVHC_COMPLIANCE: COMPLIANT; REACH/SVHC_DETAILS: SVHC LIST VERSION Jun 20, 2016; REACH/SVHC_SOURCE: MATERIAL DECLARATION; REACH/SVHC_STATUS: UNAFFECTED; ROHS: Exempt; Rated Current: N/A; Rated Power: 0.063W; Rated Voltage: 50V; Resistor Type: THICK FILM; Revision: R021; RoHS Status: ROHS_COMPLIANT; Rtd Current: N/A; Rtd Power: 0.063W; Rtd Voltage: 50V; Status: Released; Texas Part Status: Under Review; Type: Resistor; Vendor: VISHAY; Vendor Part Number: CRCW04022K20JNED; Vendor Part Status: Active; WEIGHT: 0.00065g
R55 R56 = RESISTOR: RESISTOR, THICK FILM, 100, -5%/+5%, 0.063W, 50V, -55DEGC/+155DEGC, 0402, SMD; Additional Datasheet URL: N/A; AutoDoc File: https://notefied-dynamic-precision.com/DB/Apps/Desktop/Item/Object.aspx?id=114555; BU Name: TEXAS INSTRUMENTS NORWAY; Budget Currency: USD; Budget Price: 0.0014; Budgetary Price: 0.0014 USD; Client Status: UNDER_REVIEW; Country of Origin: United States; Datasheet URL: https://www.vishay.com/docs/20035/dcrcwe3.pdf; Datasheet URL 1: http://www.vishay.com/docs/20035/dcrcwe3.pdf; Datasheet URL 2: N/A; Definied Quality: INDUSTRIAL; Esd Level: N/A; Exclusive for Customers: TEXAS INSTRUMENTS NORWAY; Lead Time: 16; LifeCycle Status: ACTIVE; MPN: RESISTOR_0402_100_+/-5%_50V_0.063W_M_+/-200ppm; MPN Status: ACTIVE; MSL: N/A; MTBF: N/A; MTBF Standard: N/A; Manufacturer: MANUFACTURER SELECTION; Mass: 0.00065g; Max Oper Temp: +155DEGC; Max TC: +200PPM/DEGC; Max Tol: +5%; Maximum Operating Temperature: +155DEGC; Maximum Temperature Coefficient: +200PPM/DEGC; Maximum Tolerance: +5%; Min Oper Temp: -55DEGC; Min TC: -200PPM/DEGC; Min Tol: -5%; Minimum Operating Temperature: -55DEGC; Minimum Temperature Coeficient: -200PPM/DEGC; Minimum Tolerance: -5%; Mounting Type: SMD; NOTE Status: PREFERRED; NOTEfied URL: https://notefied-dynamic-precision.com/NOTEfiedWebInterface/part/show?partNumber=01-22482; Notes: Standard item: Duplicate Reason: custom footprint for TEXAS INSTRUMENTS NORWAY.; Old Footprint: RESC1005X40N; PCB Package: 0402; Packing Size: 10000; Packing Type: Tape & Reel; Part Number: 01-22482; Part Type: Resistor|0402|STANDARD; REACH/SVHC Compliance: Compliant; REACH/SVHC Details: SVHC List Version Jun 20, 2016; REACH/SVHC Source: Material Declaration; REACH/SVHC Status: Unaffected; REACH/SVHC_COMPLIANCE: COMPLIANT; REACH/SVHC_DETAILS: SVHC LIST VERSION Jun 20, 2016; REACH/SVHC_SOURCE: MATERIAL DECLARATION; REACH/SVHC_STATUS: UNAFFECTED; ROHS: Exempt; Rated Current: N/A; Rated Power: 0.063W; Rated Voltage: 50V; Resistor Type: THICK FILM; Revision: R024; RoHS Status: ROHS_COMPLIANT; Rtd Current: N/A; Rtd Power: 0.063W; Rtd Voltage: 50V; Status: Released; Texas Part Status: Under Review; Type: Resistor; Vendor: VISHAY; Vendor Part Number: CRCW0402100RJNED; Vendor Part Status: Active; WEIGHT: 0.00065g
R66 R67 = RESISTOR: RESISTOR, THICK FILM, 3.3k, -5%/+5%, 0.063W, 50V, -55DEGC/+155DEGC, 0402, SMD; Additional Datasheet URL: N/A; AutoDoc File: https://notefied-dynamic-precision.com/DB/Apps/Desktop/Item/Object.aspx?id=114561; BU Name: TEXAS INSTRUMENTS NORWAY; Budget Currency: EUR; Budget Price: 0.014; Budgetary Price: 0.014 EUR; Client Status: UNDER_REVIEW; Country of Origin: Israel; Datasheet URL: https://www.vishay.com/docs/20035/dcrcwe3.pdf; Datasheet URL 1: http://www.vishay.com/docs/20035/dcrcwe3.pdf; Datasheet URL 2: N/A; Definied Quality: INDUSTRIAL; Esd Level: N/A; Exclusive for Customers: TEXAS INSTRUMENTS NORWAY; Lead Time: 18; LifeCycle Status: ACTIVE; MPN: RESISTOR_0402_3.3k_+/-5%_50V_0.063W_M_+/-200ppm; MPN Status: ACTIVE; MSL: N/A; MTBF: N/A; MTBF Standard: N/A; Manufacturer: MANUFACTURER SELECTION; Mass: 0.00065g; Max Oper Temp: +155DEGC; Max TC: +200PPM/DEGC; Max Tol: +5%; Maximum Operating Temperature: +155DEGC; Maximum Temperature Coefficient: +200PPM/DEGC; Maximum Tolerance: +5%; Min Oper Temp: -55DEGC; Min TC: -200PPM/DEGC; Min Tol: -5%; Minimum Operating Temperature: -55DEGC; Minimum Temperature Coeficient: -200PPM/DEGC; Minimum Tolerance: -5%; Mounting Type: SMD; NOTE Status: PREFERRED; NOTEfied URL: https://notefied-dynamic-precision.com/NOTEfiedWebInterface/part/show?partNumber=01-22488; Notes: Standard item: Duplicate Reason: custom footprint for TEXAS INSTRUMENTS NORWAY.; Old Footprint: RESC1005X40N; PCB Package: 0402; Packing Size: 10000; Packing Type: Tape & Reel; Part Number: 01-22488; Part Type: Resistor|0402|STANDARD; REACH/SVHC Compliance: Compliant; REACH/SVHC Details: SVHC List Version Jun 20, 2016; REACH/SVHC Source: Material Declaration; REACH/SVHC Status: Unaffected; REACH/SVHC_COMPLIANCE: COMPLIANT; REACH/SVHC_DETAILS: SVHC LIST VERSION Jun 20, 2016; REACH/SVHC_SOURCE: MATERIAL DECLARATION; REACH/SVHC_STATUS: UNAFFECTED; ROHS: Exempt; Rated Current: N/A; Rated Power: 0.063W; Rated Voltage: 50V; Resistor Type: THICK FILM; Revision: R021; RoHS Status: ROHS_COMPLIANT; Rtd Current: N/A; Rtd Power: 0.063W; Rtd Voltage: 50V; Status: Released; Texas Part Status: Under Review; Type: Resistor; Vendor: VISHAY; Vendor Part Number: CRCW04023K30JNED; Vendor Part Status: Active; WEIGHT: 0.00065g
SW1 SW2 = SWITCH_TACT_V2: SWITCH, TACT, 0.05A@12VDC, 0.05A@250VAC, SMD; ALT_SYMBOLS: SW_1188E1K2V_A2L,SW_1188E1K2V_A2M; Additional Datasheet URL: http://www.dip.com.tw/en/en-product-information/en-switch004/item/2445-1188; AutoDoc File: http://notefied-dynamic-precision.com/DB/Apps/Desktop/Item/Object.aspx?id=104642; CLASS: IC; Country of Origin: China,Vietnam; Datasheet URL: http://www.dip.com.tw/en/en-product-information/en-switch004/item/download/2483_bfc264bcfe9982a2b01570916dd931c3; Datasheet URL 1: N/A; Datasheet URL 2: http://www.dip.com.tw/en/en-product-information/en-switch004; FPLIST: SW_1188E1K2V_A2N,SW_1188E1K2V_A2L,SW_1188E1K2V_A2M; MPN: 1188E-1K2-V-TR; MPN Status: ACTIVE; Manufacturer: DIPTRONICS; Mass: N/A; Max Oper Temp: +70DEGC; Maximum Operating Temperature: +70DEGC; Min Oper Temp: -25DEGC; Minimum Operating Temperature: -25DEGC; Mounting Type: SMD; NOTE Status: PREFERRED; NOTEfied URL: https://notefied-dynamic-precision.com/NOTEfiedWebInterface/part/show?partNumber=08-00293; Packing Size: 1500; Packing Type: Tape & Reel; Part Number: 08-00293; Part Type: Switch|TACTILE; REACH/SVHC Compliance: Compliant; REACH/SVHC Details: SVHC List Version Dec 17, 2015; REACH/SVHC Source: REACH Declaration; REACH/SVHC Status: Unaffected; ROHS: Compliant; Rated Current: 0.05A; Rated Voltage: 12VDC; Revision: R020; RoHS Status: ROHS_COMPLIANT; Rtd Current: 0.05A; Rtd Voltage: 12V; Status: Released; Texas Part Status: Under Review; Type: Switch; Vendor: DIPTRONICS; Vendor Part Number: 1188E-1K2-V-TR; Vendor Part Status: Active
U1 = IC_CC2340R52E0RHB_VQFN32: IC, CUSTOM, TEXAS INSTRUMENTS, CC2340R52E0RHB, VQFN32-EP, SMD; ALT_SYMBOLS: QFNFC50P500X500X100-33B2L,QFNFC50P500X500X100-33B2M; Additional Datasheet URL: N/A; Datasheet URL: N/A; Exclusive for Customers: TEXAS INSTRUMENTS NORWAY; Mass: N/A; Maximum Operating Temperature: N/A; Minimum Operating Temperature: N/A; Mounting Type: SMD; NOTEfied URL: https://notefied-dynamic-precision.com/NOTEfiedWebInterface/part/show?partNumber=18-37032; Notes: Custom item; PCB Package: VQFN32-EP; Packing Size: N/A; Packing Type: Missing Info; Part Number: 18-37032; Part Type: IC|CUSTOM; REACH/SVHC Compliance: Missing Info; REACH/SVHC Details: N/A; REACH/SVHC Source: N/A; REACH/SVHC Status: Missing Info; ROHS: Missing Info; Revision: R001; Status: Released; Texas Part Status: Under Review; Type: IC; Vendor: TEXAS INSTRUMENTS; Vendor Part Status: Preliminary
U3 = IC_FLASH_MX25R8035F_USON8: IC, MEMORY, FLASH, SERIAL, 8Mbit, 1.65V TO 3.6V, USON8, SMD; ALT_SYMBOLS: SON50P300X200X60-9B2L,SON50P300X200X60-9B2M; Additional Datasheet URL: https://www.macronix.com/en-us/products/NOR-Flash/Serial-NOR-Flash/Pages/spec.aspx?p=MX25R8035F&m=Serial%20NOR%20Flash&n=PM2164; AutoDoc File: http://notefied-dynamic-precision.com/DB/Apps/Desktop/Item/Object.aspx?id=104624; Budgetary Price: 0.42218 USD; Country of Origin: Taiwan; Datasheet URL: https://www.macronix.com/Lists/Datasheet/Attachments/7934/MX25R8035F,%20Wide%20Range,%208Mb,%20v1.6.pdf; Datasheet URL 1: N/A; Datasheet URL 2: http://www.macronix.com/Lists/DataSheet/Attachments/2570/MX25R8035F,%20Wide%20Range,%208Mb,%20v0.04.pdf; FPLIST: SON50P300X200X60-9B2N,SON50P300X200X60-9B2L,SON50P300X200X60-9B2M; Lead Time: 10; MPN Status: ACTIVE; Manufacturer: MACRONIX; Mass: N/A; Max Oper Temp: +85DEGC; Maximum Operating Temperature: +85DEGC; Min Oper Temp: -40DEGC; Minimum Operating Temperature: -40DEGC; Mounting Type: SMD; NOTE Status: PREFERRED; NOTEfied URL: https://notefied-dynamic-precision.com/NOTEfiedWebInterface/part/show?partNumber=18-31726; PCB Package: uSON8; Packing Size: 100; Packing Type: Tube; Part Number: 18-31726; Part Type: IC|MEMORY|FLASH|OTHER; REACH/SVHC Compliance: Compliant; REACH/SVHC Details: N/A; REACH/SVHC Source: REACH Declaration & Material Declaration; REACH/SVHC Status: Unaffected; ROHS: Compliant; Rated Voltage: 1.65V TO 3.6V; Revision: R022; RoHS Status: ROHS_COMPLIANT; Rtd Voltage: 1.65V TO 3.6V; Status: Released; Texas Part Status: Under Review; Type: IC; Vendor: MACRONIX; Vendor Part Status: Active
CR8 CR9 = DIODE_TVS_TPD6E004_QFN8_V1: DIODE, PROTECTION, ESD ARRAY - 6 CHANNELS, 0.9V TO 5.5V, VBR:7V, -40DEGC/+85DEGC, QFN8, SMD; ALT_SYMBOLS: QFNFC50P150X150X60-8A2L,QFNFC50P150X150X60-8A2M; Additional Datasheet URL: https://www.ti.com/lit/ml/mpqf207e/mpqf207e.pdf; AutoDoc File: https://notefied-dynamic-precision.com/DB/Apps/Desktop/Item/Object.aspx?id=74721; BU Name: DYNAMIC PRECISION GDANSK; Budget Currency: USD; Budget Price: 0.27; Budgetary Price: 0.295 USD; CLASS: IC; Client Status: UNDER_REVIEW; Country of Origin: China,Thailand; Datasheet URL: https://www.ti.com/lit/gpn/tpd6e004; Datasheet URL 1: http://www.ti.com/lit/ds/symlink/tpd6e004.pdf; Datasheet URL 2: http://www.ti.com/litv/pdf/mpqf207b; FPLIST: QFN50P150X150X60-8N,QFN50P150X150X60-8AN; Lead Time: 10; Mass: 0.0033g; Max Oper Temp: +85DEGC; Maximum Operating Temperature: +85DEGC; Min Oper Temp: -40DEGC; Minimum Operating Temperature: -40DEGC; Mounting Type: SMD; NOTEfied URL: https://notefied-dynamic-precision.com/NOTEfiedWebInterface/part/show?partNumber=14-05493; PCB Package: QFN8; Packing Size: 3000; Packing Type: Tape & Reel; Part Number: 14-05493; Part Type: Diode|PROTECTION; REACH/SVHC Compliance: Compliant; REACH/SVHC Details: SVHC List Version Jun 20, 2016; REACH/SVHC Source: Material Declaration; REACH/SVHC Status: Unaffected; ROHS: Compliant; Rated Power: N/A; Rated Voltage: 7V; Revision: R027; RoHS Status: ROHS_COMPLIANT; Rtd Power: N/A; Rtd Voltage: 7V; Status: Released; Texas Part Status: Under Review; Type: Diode; Vendor: TEXAS INSTRUMENTS; Vendor Part Number: TPD6E004RSER; Vendor Part Status: Active; Weight: 0.0033g
P3 = CONN_HEADER_2X10_J_S_V1: CONNECTOR, HEADER, FEMALE, RIGHT ANGLE, 2 ROWS, 20 PINS, PITCH 2.54mm, PTH; ALT_SYMBOLS: CNT_CNTF254210GD85032_A2A,CNT_CNTF254210GD85032_A2C; Additional Datasheet URL: http://yccnt.com/cpzx/info_56.aspx?itemid=1264&lcid=28&cid=29; Datasheet URL: http://yccnt.com/uploadfiles/2017/08/201708261737473747.pdf; Maximum Operating Temperature: +105DEGC; Minimum Operating Temperature: -40DEGC; Mounting Type: PTH; NOTEfied URL: https://notefied-dynamic-precision.com/NOTEfiedWebInterface/part/show?partNumber=06-08434; Number of Positions: 20; Number of Rows: 2; Packing Size: N/A; Packing Type: Missing Info; Part Number: 06-08434; Part Type: Connector|HEADER|STANDARD; Pitch: 2.54mm; REACH/SVHC Compliance: Missing Info; REACH/SVHC Details: N/A; REACH/SVHC Source: N/A; REACH/SVHC Status: Missing Info; ROHS: Compliant; Rated Current: 3A; Rated Voltage: 500V; Revision: R004; Status: Released; Texas Part Status: Under Review; Type: Connector; Vendor: CNT CONNECTORS; Vendor Part Status: Active
P4 = CONN_HEADER_2X5: CONNECTOR, HEADER, MALE, STRAIGHT, 2 ROWS, 10 PINS, PITCH 1.27mm, SMD; ALT_SYMBOLS: SAMTEC_FTSH10501FDVK_A2L,SAMTEC_FTSH10501FDVK_A2M; Additional Datasheet URL: http://suddendocs.samtec.com/prints/ftsh-1xx-xx-xxx-dv-xxx-xxx-mkt.pdf; AutoDoc File: http://notefied-dynamic-precision.com/DB/Apps/Desktop/Item/Object.aspx?id=50836; Budget Currency: USD; Budget Price: 1.700; Budgetary Price: 1.7 USD; CLASS: IO; Country of Origin: China,Costa Rica,Malaysia,Singapore,United States; Datasheet URL: http://suddendocs.samtec.com/catalog_english/ftsh_smt.pdf; Datasheet URL 1: http://www.samtec.com/documents/webfiles/cpdf/FTSH-1XX-XX-XXX-DV-XXX-MKT.pdf; Datasheet URL 2: http://www.samtec.com/documents/webfiles/pdf/FTSH_SMT.PDF; FPLIST: SAMTEC_FTSH-105-01-F-DV-K-10N,SAMTEC_FTSH-105-01-F-DV-K-10L,SAMTEC_FTSH-105-01-F-DV-K-10M; Lead Time: 2; LifeCycle Status: MATURITY; MPN Status: ACTIVE; Manufacturer: SAMTEC; Mass: 0.65614g; Max Oper Temp: +125DEGC; Maximum Operating Temperature: +125DEGC; Min Oper Temp: -55DEGC; Minimum Operating Temperature: -55DEGC; Mounting Type: SMD; NOTE Status: PREFERRED; NOTEfied URL: https://notefied-dynamic-precision.com/NOTEfiedWebInterface/part/show?partNumber=06-00166; No Of Pos: 10; No Of Rows: 2; Number of Positions: 10; Number of Rows: 2; Old Footprint: SAMTEC_FTSH-105-01-F-DV-K-10N,CONN_MALE_2X5; Packing Size: 92; Packing Type: Tube; Part Number: 06-00166; Part Type: Connector|HEADER|STANDARD; Pitch: 1.27mm; REACH/SVHC Compliance: Compliant; REACH/SVHC Details: SVHC List Version Jun 20, 2016; REACH/SVHC Source: Material Declaration; REACH/SVHC Status: Unaffected; ROHS: Compliant; Rated Current: 1.75A; Revision: R008; RoHS Status: ROHS_COMPLIANT; Rtd Current: 1.75A; Status: Released; Texas Part Status: Under Review; Type: Connector; Vendor: SAMTEC; Vendor Part Status: Active; WEIGHT: 0.65614g
U4 = IC_EEPROM_CAT24C08_TSOT23-5: IC, MEMORY, EEPROM, SERIAL, I2C, CMOS, 8kbit, 1.7V TO 5.5V, TSOT23-5, SMD; ALT_SYMBOLS: SOT95P280X100-5A2L,SOT95P280X100-5A2M; Additional Datasheet URL: https://www.onsemi.com/pub/Collateral/419AE.PDF; Budgetary Price: 0.1867 USD; Datasheet URL: https://www.onsemi.com/pub/Collateral/CAT24C01-D.PDF; Mass: 0.01268g; Maximum Operating Temperature: +85DEGC; Minimum Operating Temperature: -40DEGC; Mounting Type: SMD; NOTEfied URL: https://notefied-dynamic-precision.com/NOTEfiedWebInterface/part/show?partNumber=18-36044; PCB Package: TSOT23-5; Packing Size: 3000; Packing Type: Tape & Reel; Part Number: 18-36044; Part Type: IC|MEMORY|ROM|EEPROM|SERIAL|I2C; REACH/SVHC Compliance: Compliant; REACH/SVHC Details: SVHC List Version Jan 16, 2020; REACH/SVHC Source: REACH Declaration; REACH/SVHC Status: Unaffected; ROHS: Compliant; Rated Voltage: 1.7V TO 5.5V; Revision: R004; Status: Released; Texas Part Status: Under Review; Type: IC; Vendor: ON SEMICONDUCTOR; Vendor Part Number: CAT24C08TDI-GT3; Vendor Part Status: Active
FIDU1-FIDU6 = FIDMARK: NON COMPONENT, FIDUCIAL MARK, ROUND 1.27MM, SMD; Additional Datasheet URL: N/A; CLASS: IO; Country of Origin: Missing Info; Datasheet URL: N/A; Mass: N/A; Mounting Type: SMD; NOTEfied URL: https://notefied-dynamic-precision.com/NOTEfiedWebInterface/part/show?partNumber=19-00300; Packing Size: N/A; Packing Type: Missing Info; Part Number: 19-00300; Part Type: Non Component|FIDUCIAL; ROHS: Missing Info; Revision: R008; Status: Released; Texas Part Status: Under Review; Type: Non Component; Vendor: NON_COMPONENT; Vendor Part Number: FIDUCIAL_1.27mm; Vendor Part Status: Active
LBL1 = TI_LOGO_V1: NON COMPONENT, LABEL, TEXAS INSTRUMENTS LOGO; Additional Datasheet URL: N/A; AutoDoc File: https://notefied-dynamic-precision.com/DB/Apps/Desktop/Item/Object.aspx?id=87770; BU Name: TEXAS INSTRUMENTS NORWAY; Country of Origin: Missing Info; Datasheet URL: N/A; Exclusive for Customers: TEXAS INSTRUMENTS NORWAY; Mass: N/A; Mounting Type: Not Apply; NOTEfied URL: https://notefied-dynamic-precision.com/NOTEfiedWebInterface/part/show?partNumber=19-00350; Notes: Custom Item; Packing Size: N/A; Packing Type: Missing Info; Part Number: 19-00350; Part Type: Non Component|LABEL; ROHS: Missing Info; Revision: R009; Status: Released; Texas Part Status: Under Review; Type: Non Component; Vendor: NON_COMPONENT; Vendor Part Status: Active
LBL2 = TRASH_V2: NON COMPONENT, LABEL, TRASH 7mm; Additional Datasheet URL: N/A; Country of Origin: Missing Info; Datasheet URL: N/A; Mass: N/A; Mounting Type: Not Apply; NOTEfied URL: https://notefied-dynamic-precision.com/NOTEfiedWebInterface/part/show?partNumber=19-01044; Packing Size: N/A; Packing Type: Missing Info; Part Number: 19-01044; Part Type: Non Component|LABEL; ROHS: Missing Info; Revision: R003; Status: Released; Texas Part Status: Under Review; Type: Non Component; Vendor: NON_COMPONENT; Vendor Part Status: Active
LBL3 = ESD_LABEL: NON COMPONENT, LABEL, ESD, 5 X 5 mm; Additional Datasheet URL: N/A; Country of Origin: Missing Info; Datasheet URL: N/A; Mass: N/A; Maximum Operating Temperature: N/A; Minimum Operating Temperature: N/A; Mounting Type: Not Apply; NOTEfied URL: https://notefied-dynamic-precision.com/NOTEfiedWebInterface/part/show?partNumber=19-00471; Packing Size: N/A; Packing Type: Missing Info; Part Number: 19-00471; Part Type: Non Component|LABEL; ROHS: Not Applicable; Revision: R006; Status: Released; Type: Non Component; Vendor: NON_COMPONENT; Vendor Part Status: Active
LBL5 = LABEL_FOR_EVALUATOIN_ONLY: NON COMPONENT, LABEL, FOR EVALUATION ONLY, NOT FCC APPROVED FOR RESALE; Additional Datasheet URL: N/A; AutoDoc File: https://notefied-dynamic-precision.com/DB/Apps/Desktop/Item/Object.aspx?id=115268; BU Name: TEXAS INSTRUMENTS NORWAY; Datasheet URL: N/A; Exclusive for Customers: TEXAS INSTRUMENTS NORWAY; Maximum Operating Temperature: N/A; Minimum Operating Temperature: N/A; Mounting Type: Not Apply; NOTEfied URL: https://notefied-dynamic-precision.com/NOTEfiedWebInterface/part/show?partNumber=19-00830; Notes: Custom Item; Part Number: 19-00830; Part Type: Non Component|LABEL; REACH/SVHC Compliance: Missing Info; REACH/SVHC Details: N/A; REACH/SVHC Source: N/A; REACH/SVHC Status: Missing Info; ROHS: Missing Info; Revision: R009; Status: Released; Texas Part Status: Under Review; Type: Non Component; Vendor: NON_COMPONENT; Vendor Part Status: Active
M1 M2 = MECH_SHUNT_JUMPER_V1: MECHANIC, SHUNT, CURRENT RATING 4.3A PER PIN, 2.54 X 5.08 X 6.1mm, BLACK; Additional Datasheet URL: http://suddendocs.samtec.com/prints/snt-100-xx-x-x-mkt.pdf; AutoDoc File: https://notefied-dynamic-precision.com/DB/Apps/Desktop/Item/Object.aspx?id=104092; BU Name: DYNAMIC PRECISION GDANSK; Budget Currency: USD; Budget Price: 0.146; Budgetary Price: 0.146 USD; Client Status: UNDER_REVIEW; Country of Origin: China,Costa Rica,Malaysia,Singapore,United States; Datasheet URL: http://suddendocs.samtec.com/catalog_english/snt.pdf; Datasheet URL 1: http://suddendocs.samtec.com/catalog_english/snt.pdf; Datasheet URL 2: http://suddendocs.samtec.com/prints/snt-100-xx-x-x-mkt.pdf; Lead Time: 1; Mass: 0.11724g; Max Oper Temp: +125DEGC; Maximum Operating Temperature: +125DEGC; Min Oper Temp: -55DEGC; Minimum Operating Temperature: -55DEGC; Mounting Type: Not Apply; NOTEfied URL: https://notefied-dynamic-precision.com/NOTEfiedWebInterface/part/show?partNumber=19-00498; Packing Size: 1; Packing Type: Bulk; Part Number: 19-00498; Part Type: Mechanic|SHUNT; REACH/SVHC Compliance: Compliant; REACH/SVHC Details: SVHC List Version Dec 17, 2015; REACH/SVHC Source: Material Declaration; REACH/SVHC Status: Unaffected; REACH/SVHC_COMPLIANCE: COMPLIANT; REACH/SVHC_DETAILS: SVHC LIST VERSION Dec 17, 2015; REACH/SVHC_SOURCE: MATERIAL DECLARATION; REACH/SVHC_STATUS: UNAFFECTED; ROHS: Compliant; Rated Current: 4.3A; Revision: R011; RoHS Status: ROHS_COMPLIANT; Rtd Current: 4.3A; Status: Released; Texas Part Status: Under Review; Type: Mechanic; Vendor: SAMTEC; Vendor Part Status: Active; Weight: 0.11724g
M3-M6 = MECH_SPACERS_SUPPORT_V1: MECHANIC, ACCESSORY, SPACER SUPPORT, PCB DIA. 3mm, NYLON 66, PTH; Additional Datasheet URL: N/A; Datasheet URL: N/A; Maximum Operating Temperature: N/A; Minimum Operating Temperature: N/A; Mounting Type: PTH; NOTEfied URL: https://notefied-dynamic-precision.com/NOTEfiedWebInterface/part/show?partNumber=13-04664; Part Number: 13-04664; Part Type: Mechanic|ACCESSORY; REACH/SVHC Compliance: Compliant; REACH/SVHC Details: SVHC List Version Jul 7, 2017; REACH/SVHC Source: REACH Declaration; REACH/SVHC Status: Unaffected; ROHS: Compliant; Revision: R004; Status: Released; Texas Part Status: Under Review; Type: Mechanic; Vendor: SUZHOU SOLY ELECTRICIAN; Vendor Part Status: Active
MH1-MH4 = HOLE_PTH: NON COMPONENT, HOLE 3.2mm, PLATED HOLE, PTH; Additional Datasheet URL: N/A; Country of Origin: Missing Info; Datasheet URL: N/A; Mass: N/A; Mounting Type: PTH; NOTEfied URL: https://notefied-dynamic-precision.com/NOTEfiedWebInterface/part/show?partNumber=19-00083; Packing Size: N/A; Packing Type: Missing Info; Part Number: 19-00083; Part Type: Non Component|HOLE|PLATED; ROHS: Missing Info; Revision: R007; Status: Released; Type: Non Component; Vendor: NON_COMPONENT; Vendor Part Number: HOLE_3.2mm_PLATED; Vendor Part Status: Active
MH5 = HOLE_PTH: NON COMPONENT, HOLE 1.1mm, PLATED, PAD SIZE 1.7mm; Additional Datasheet URL: N/A; Country of Origin: Missing Info; Datasheet URL: N/A; Mass: N/A; Mounting Type: NOT APPLY; NOTEfied URL: https://notefied-dynamic-precision.com/NOTEfiedWebInterface/part/show?partNumber=19-00062; Packing Size: N/A; Packing Type: Missing Info; Part Number: 19-00062; Part Type: Non Component|HOLE|PLATED; ROHS: Missing Info; Revision: R007; Status: Released; Type: Non Component; Vendor: NON_COMPONENT; Vendor Part Number: HOLE_1.1mm_PLATED; Vendor Part Status: Active

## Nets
5V0_BP: J1.2 P3.3 P5.1 U4.4(VCC)
GND: C55.2 CR1.1(C) CR2.1(C) CR8.4(GND) CR9.4(GND) J1.4 J2.2 MH3.1 MH4.1 MH5.1 P1.2 P1.3 P3.1 P3.2 P3.8 P3.14 P3.20 P4.3 P4.5 P4.9 P5.2 P5.3 SW1.1 SW1.2 SW1.3 SW2.1 SW2.2 SW2.4 U3.4(GND) U3.9(EGP) U4.2(VSS) U4.5(WP) ; also on sheet 1
BP_RESET: J2.11 R52.1
BTN1: P6.3 R56.2
BTN2: P7.3 R55.2
DIO1_RTS: J2.9 U1.18(DIO1_A4)
DIO3: J1.15 ; also on sheet 1
DIO4: J1.9 ; also on sheet 1
DIO5_A2: J1.14 R21.1 U1.23(DIO5_A2)
DIO6_FLASH_CS: J2.5 R24.1 U1.26(DIO6_A1) U3.1(nCS)
DIO8_SDA: P7.2 P7.4 U1.2(DIO8)
DIO11_CS: J2.6 U1.3(DIO11)
DIO12_MISO: J2.14 U1.4(DIO12) U3.2(SO/SIO1)
DIO13_MOSI: J2.12 U1.5(DIO13) U3.5(SI/SIO0)
DIO14_RLED: J2.3 P2.2 U1.7(DIO14)
DIO18_SCLK: J1.13 U1.10(DIO18) U3.6(SCLK)
DIO19_GLED: J2.8 P2.4 U1.11(DIO19)
DIO21_CTS: J2.7 U1.13(DIO21_A10)
DIO23_A8: J1.6 U1.16(DIO23_A8)
DIO24_SCL: P6.2 P6.4 U1.17(DIO24_A7)
LP_RESET: J2.10 R51.1
SCL: J1.17 P6.1 R67.1
SDA: J1.19 P7.1 R66.1
WMCU_RESET: CR8.3(IO3) P3.11 P4.10 R51.2 R52.2 ; also on sheet 1
WMCU_RXD: J1.5 P3.7 U1.15(DIO22_A9)
WMCU_SWDCK: CR8.6(IO5) P3.15 P4.4 R5.2 ; also on sheet 1
WMCU_SWDIO: CR8.7(IO6) P3.13 P4.2 R4.2 ; also on sheet 1
WMCU_TXD: J1.7 P3.9 U1.12(DIO20_A11)
WMCU_VDD: CR8.8(VCC) CR9.8(VCC) J1.1 P1.1 P3.5 P4.1 R22.1 R23.1 R24.2 R25.2 R66.2 R67.2 ; also on sheet 1
XDS_BoardID_SCL: P3.6 U4.1(SCL)
XDS_BoardID_SDA: P3.4 U4.3(SDA)
XDS_GPIO3: CR9.7(IO6) P3.12 R21.2
N3109894: J2.13 R4.1
N3109960: J2.15 R5.1
N3110356: P2.1 R14.2
N3110380: P2.3 R15.2
N3110768: R56.1 SW1.4
N3110772: R55.1 SW2.3
N3110876: CR1.2(A) R15.1
N3110880: CR2.2(A) R14.1
N3111246: C55.1 R25.1 U3.8(VCC)
N3111262: R22.2 U3.7(nRST/SIO3)
N3111266: R23.2 U3.3(nWP/SIO2)

Not connected (* = marked no-connect by the designer): CR8 1(IO1)* 2(IO2)* 5(IO4)*; CR9 1(IO1)* 2(IO2)* 3(IO3)* 5(IO4)* 6(IO5)*; FIDU1 1*; FIDU2 1*; FIDU3 1*; FIDU4 1*; FIDU5 1*; FIDU6 1*; J1 3* 8* 10* 11* 12* 16 18* 20*; J2 1 4* 16 17* 18 19* 20*; MH1 1*; MH2 1*; P3 10* 16 17* 18 19*; P4 6* 7* 8*

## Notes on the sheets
sheet 2
- BoosterPack Headers and Peripherals
- 1
- 2
- 21
- 22
- 39
- 40
- 19
- 20
- 3
- 23
- 38
- 18
- 4
- 24
- 37
- 17
- 5
- 25
- 36
- 16
- 6
- 26
- 35
- 15
- 7
- 8
- 27
- 28
- 33
- 34
- 13
- 14
- 9
- 29
- 32
- 12
- 10
- 30
- 31
- 11
- Wireless MCU IO block
- Buttons / LEDs
- Place on bottom layer as DNM
- External flash
- 5V and 3V headers
sheet 3
- XDS110 Debugger Interface
- DEBUG
- Board ID
- Use P4 for debugging
  the wireless MCU with an
  external debugger
sheet 4
- Mechanical
- Labels
- Jumpers (P1)
- Fiducials
- Mounting Holes
